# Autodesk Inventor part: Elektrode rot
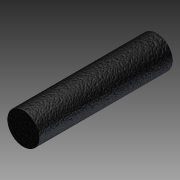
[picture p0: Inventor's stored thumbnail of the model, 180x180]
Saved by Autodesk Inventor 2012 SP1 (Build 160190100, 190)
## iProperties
Created: 2012-10
Part Number: Elektrode rot
Material: Default
Document SubType Name: Modeling
Designer: Dominic Mähling
Density: 1 g/cm^3
Author: Dominic Mähling
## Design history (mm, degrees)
derived "Funkenstrecke master.ipt"
feature "Elektrode rot::Funkenstrecke master.ipt" dims "d0" = 10
tag "Bezeichnung1"
node "Volumenkörper1"
